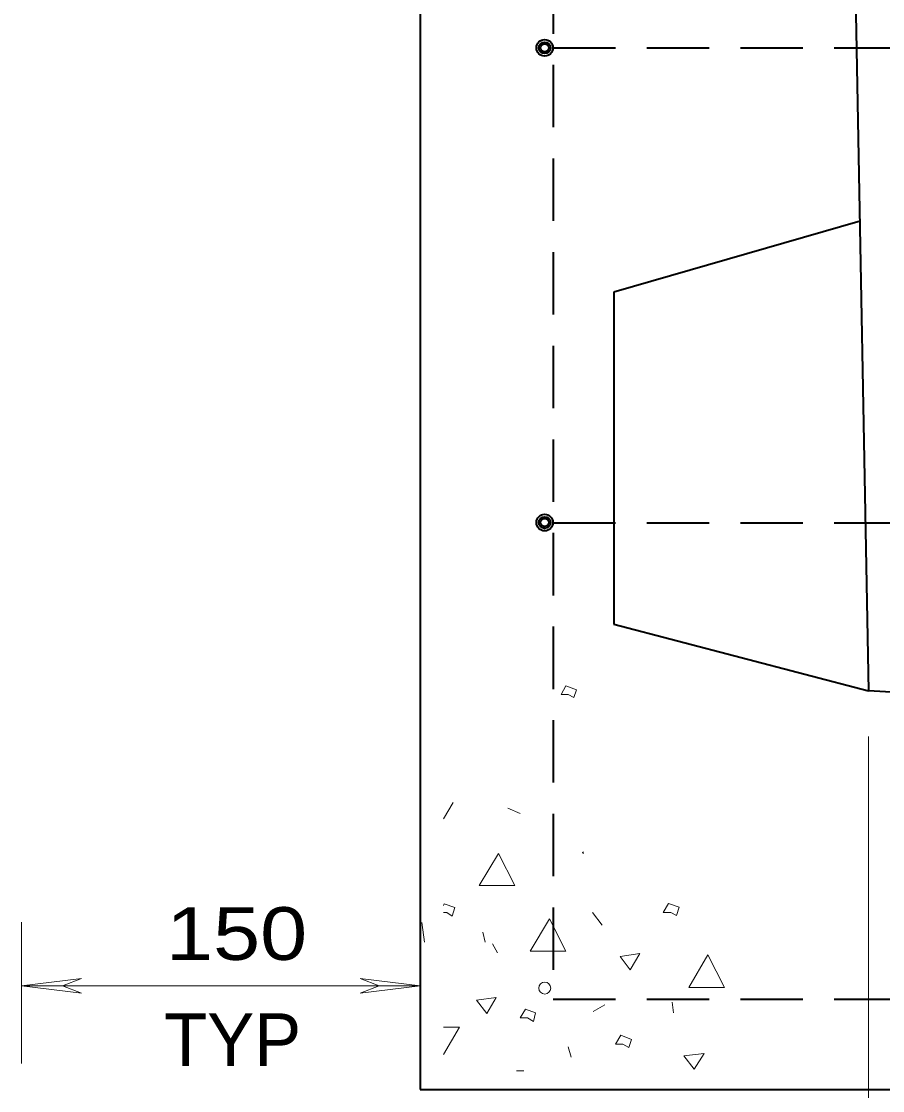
# Model space of a CAD drawing. Extents: x 312583 to 312854, y 144419 to 144597.
# Drawn here: x 312691.25 to 312703.67, y 144451.6 to 144467.02 of the extents above; entities that cross this region are included whole.
import ezdxf

# ---------------------------------------------------------------- set-up
doc = ezdxf.new("R2010")
doc.units = 0
doc.header["$LTSCALE"] = 0.3
doc.linetypes.add('MEDIUM_DASHED', pattern=[4.5, 3, -1.5])
doc.layers.add('1', color=7, linetype='Continuous', lineweight=25)
doc.layers.add('2', color=7, linetype='Continuous', lineweight=13)

msp = doc.modelspace()

# ---------------------------------------------------------------- linework, layer by layer
at = {"layer": '1', "lineweight": 40}
for p, q in [((312697.001, 144497.14), (312697.001, 144451.6154)), ((312703.119, 144475.727), (312703.464, 144457.3654)), ((312703.3414, 144464.135), (312699.7917, 144463.1154)), ((312699.7917, 144463.1154), (312699.7917, 144458.3237)), ((312699.7917, 144458.3237), (312703.464, 144457.3654)), ((312711.376, 144456.89), (312703.464, 144457.3654)), ((312697.001, 144451.6154), (312725.751, 144451.6154))]:
    msp.add_line(p, q, dxfattribs=at)
at = {"layer": '1', "linetype": 'MEDIUM_DASHED', "lineweight": 40}
for p, q in [((312698.9177, 144494.7404), (312698.9177, 144452.9187)), ((312698.9177, 144466.6344), (312723.8344, 144466.6344)), ((312698.9177, 144459.788), (312723.8344, 144459.788)), ((312698.9177, 144452.9187), (312723.8344, 144452.9187))]:
    msp.add_line(p, q, dxfattribs=at)
at = {"layer": '1', "lineweight": 13}
for p, q in [((312697.3384, 144455.5177), (312697.4764, 144455.7554)), ((312698.4424, 144455.5944), (312698.266, 144455.671)), ((312699.3547, 144455.0424), (312699.3394, 144455.0347)), ((312699.3394, 144455.0347), (312699.3547, 144455.0194)), ((312697.3384, 144454.1684), (312697.3844, 144454.1684)), ((312699.623, 144453.9844), (312699.485, 144454.1684)), ((312697.024, 144454.0227), (312697.0624, 144453.739)), ((312697.9057, 144453.8847), (312697.9364, 144453.739)), ((312698.0437, 144453.716), (312698.1127, 144453.5857)), ((312699.6614, 144452.8344), (312699.4927, 144452.7424)), ((312700.635, 144452.8727), (312700.6504, 144452.7194)), ((312697.5684, 144452.5124), (312697.3384, 144452.5124)), ((312697.3384, 144452.1214), (312697.5684, 144452.5124)), ((312699.1324, 144452.2287), (312699.1784, 144452.083)), ((312698.3887, 144451.8837), (312698.496, 144451.8837))]:
    msp.add_line(p, q, dxfattribs=at)
for points in [[(312699.1324, 144457.3117), (312699.2167, 144457.2657), (312699.255, 144457.3807), (312699.1017, 144457.4344), (312699.0327, 144457.3117)], [(312697.852, 144454.5594), (312698.3657, 144454.5594), (312698.128, 144455.0194)], [(312700.612, 144454.1684), (312700.6964, 144454.1224), (312700.7347, 144454.245), (312700.5814, 144454.2987), (312700.5047, 144454.1684)], [(312698.588, 144453.6087), (312699.1017, 144453.6087), (312698.864, 144454.0764)], [(312699.8837, 144453.532), (312700.0294, 144453.3404), (312700.1674, 144453.578)], [(312700.8727, 144453.0874), (312701.3864, 144453.0874), (312701.1487, 144453.555)], [(312697.8137, 144452.9034), (312697.9594, 144452.7117), (312698.0974, 144452.9417)], [(312698.5497, 144452.6504), (312698.634, 144452.5967), (312698.6647, 144452.7194), (312698.519, 144452.773), (312698.4424, 144452.6504)], [(312699.922, 144452.267), (312700.0064, 144452.221), (312700.0447, 144452.336), (312699.8914, 144452.3974), (312699.8147, 144452.267)], [(312700.8037, 144452.0984), (312700.9494, 144451.9067), (312701.095, 144452.1367)]]:
    msp.add_lwpolyline(points, close=True, dxfattribs=at)
msp.add_lwpolyline([(312697.3844, 144454.1684), (312697.461, 144454.1147), (312697.4994, 144454.2374), (312697.346, 144454.291), (312697.3384, 144454.268)], dxfattribs=at)
at = {"layer": '1', "lineweight": 40}
for centre, radius in [((312698.795, 144466.6363), 0.1198), ((312698.795, 144466.6363), 0.0838), ((312698.795, 144466.6363), 0.0587), ((312698.795, 144459.7909), 0.1198), ((312698.795, 144459.7909), 0.0838), ((312698.795, 144459.7909), 0.0587)]:
    msp.add_circle(centre, radius, dxfattribs=at)
at = {"layer": '1', "lineweight": 13}
msp.add_circle((312698.7952, 144453.0781), 0.0865, dxfattribs=at)
at = {"layer": '2'}
for p, q in [((312703.464, 144456.706), (312703.464, 144445.1984)), ((312691.251, 144451.991), (312691.251, 144454.0304)), ((312691.251, 144453.1104), (312692.1174, 144453.2177)), ((312691.251, 144453.1104), (312697.001, 144453.1104)), ((312691.251, 144453.1104), (312692.1174, 144453.003)), ((312692.1174, 144453.2177), (312691.8414, 144453.1104)), ((312692.1174, 144453.003), (312691.8414, 144453.1104)), ((312696.1347, 144453.2177), (312696.4107, 144453.1104)), ((312697.001, 144453.1104), (312696.1347, 144453.2177)), ((312696.1347, 144453.003), (312696.4107, 144453.1104)), ((312697.001, 144453.1104), (312696.1347, 144453.003))]:
    msp.add_line(p, q, dxfattribs=at)

# ---------------------------------------------------------------- texts
at = {"layer": '2', "width": 1.2}
msp.add_text('150 ', height=0.76, dxfattribs=at).set_placement((312693.3365, 144453.4842))
at = {"layer": '2'}
msp.add_text('TYP', height=0.76, dxfattribs=at).set_placement((312693.3085, 144451.9526))

doc.saveas('drawing.dxf')
